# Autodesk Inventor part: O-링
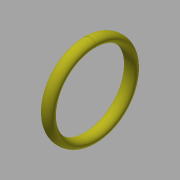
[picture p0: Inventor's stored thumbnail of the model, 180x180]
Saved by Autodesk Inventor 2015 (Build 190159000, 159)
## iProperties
Created: 2019-02
Part Number: O-링
Material: 고무
Document SubType Name: Modeling
Designer: mduedu
Density: 1 g/cm^3
Appearance: 밝은 황색
Author: mduedu
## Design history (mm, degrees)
sketch "스케치1"
  geometry: L1 (-2.35, 0)-(2.35, 0); L2 (2.35, 0)-(2.35, 17); L3 (2.35, 17)-(-2.35, 17); L4 (-2.35, 17)-(-2.35, 0); L5 (-2.35, 14)-(2.35, 14); 3 further points; 1 other entity
  constraints: 10 end point, 4 horizontal, 2 parallel, 2 perpendicular, 2 point on line, 2 vertical, 1 coincident, 1 midpoint, 2 other
  dimensions: "d0" = 34 diameter of L3 L1; "d2" = 4.7 distance of L2.end L3.end; "d3" = 28 diameter of L5 L1
revolve "회전1" sketch "스케치1" stored, may be unused: angle "d4" = 90 deg
node "솔리드1"
